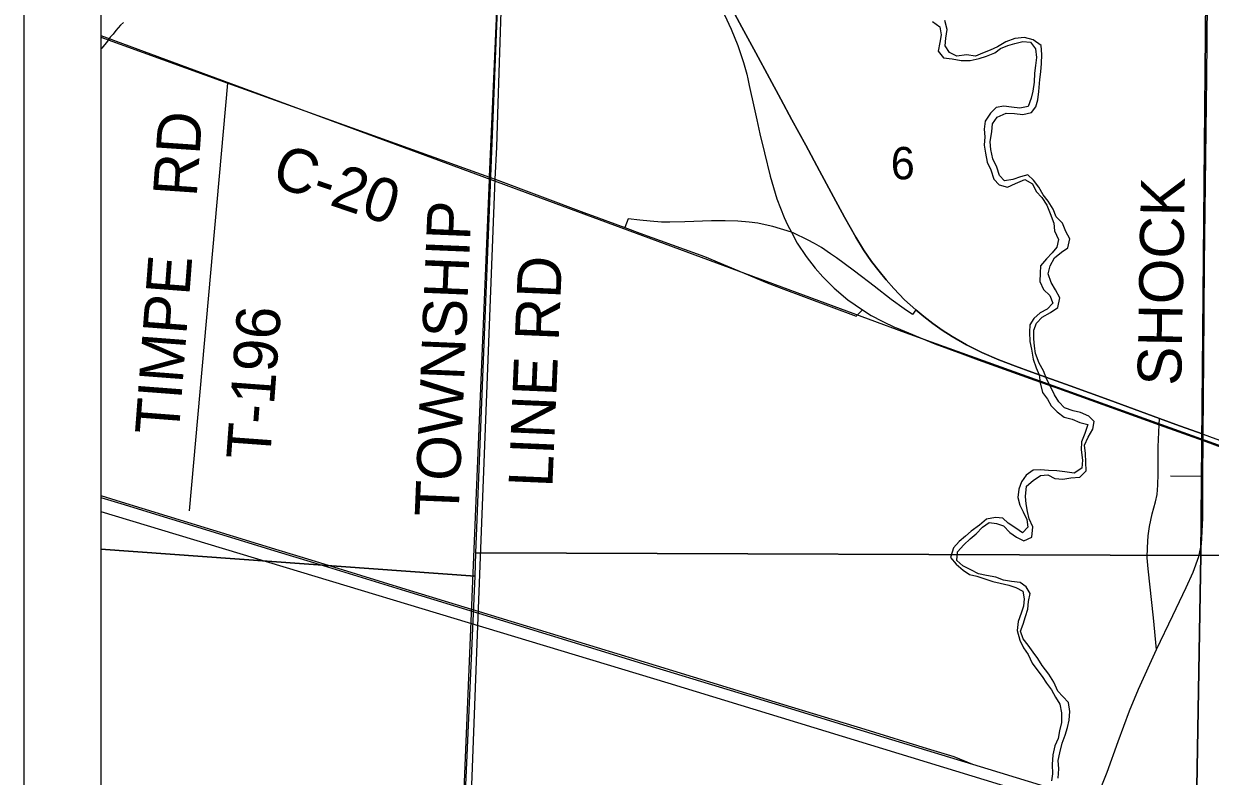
# Model space of a CAD drawing. Extents: x 0 to 34, y 0 to 22.
# Drawn here: x 2 to 3.538, y 19.175 to 20.151 of the extents above; entities that cross this region are included whole.
import ezdxf

# ---------------------------------------------------------------- set-up
doc = ezdxf.new("R2010")
doc.units = 0
for name, color, linetype in [('Default', 7, 'Continuous'), ('GM_X_County_Road', 7, 'Continuous'), ('GM_X_County_Road_Text', 7, 'Continuous'), ('GM_X_Interchange_Ramps', 7, 'Continuous'), ('GM_X_Minor_River', 7, 'Continuous'), ('GM_X_Rail_Line', 7, 'Continuous'), ('GM_X_Section', 7, 'Continuous'), ('GM_X_Section_Text', 7, 'Continuous'), ('GM_X_State_Route', 7, 'Continuous'), ('GM_X_Township', 7, 'Continuous'), ('GM_X_Township_Road', 7, 'Continuous'), ('GM_X_Township_Road_Text', 7, 'Continuous'), ('GM_X_US_Route', 7, 'Continuous'), ('SH_Cut_Line', 7, 'Continuous'), ('SH_Data', 7, 'Continuous')]:
    doc.layers.add(name, color=color, linetype=linetype)

msp = doc.modelspace()

# ---------------------------------------------------------------- linework, layer by layer
at = {"layer": 'Default'}
for points in [[(2.1, 20.3771), (2.1, 19.4698), (2.5849, 19.435), (2.5858, 19.465), (2.6217, 20.3656)], [(2.1, 19.4698), (2.1, 18.4416), (2.54, 18.4332), (2.5413, 18.4578), (2.5849, 19.435)]]:
    msp.add_lwpolyline(points, close=True, dxfattribs=at)
at = {"layer": 'GM_X_County_Road'}
for p, q in [((2.5885, 19.3706), (2.6108, 19.9494)), ((2.5733, 18.9746), (2.5885, 19.3706))]:
    msp.add_line(p, q, dxfattribs=at)
for points in [[(2.6108, 19.9494), (2.6132, 19.9909), (2.6147, 20.0477), (2.6187, 20.1666), (2.6231, 20.2904), (2.6255, 20.36), (2.6264, 20.3623)], [(2.1, 20.1336), (2.2644, 20.0739), (2.6038, 19.9519), (2.6108, 19.9494)], [(2.6108, 19.9494), (2.7293, 19.9049), (2.7321, 19.9039)], [(2.7321, 19.9039), (2.779, 19.8867), (2.7985, 19.8796)], [(2.7985, 19.8796), (2.8823, 19.8491), (2.9633, 19.8151)]]:
    msp.add_lwpolyline(points, dxfattribs=at)
at = {"layer": 'GM_X_Interchange_Ramps'}
for points in [[(3.0946, 19.8164), (3.0856, 19.8232), (3.075, 19.8317), (3.0533, 19.8474), (3.0456, 19.8528), (3.0337, 19.8608), (3.025, 19.866), (3.0158, 19.871), (2.9982, 19.8793), (2.9948, 19.8808), (2.971, 19.888), (2.961, 19.8904), (2.9513, 19.8922), (2.9401, 19.8938), (2.9255, 19.895), (2.9091, 19.8955), (2.8915, 19.8953), (2.8568, 19.894), (2.8375, 19.8937), (2.8265, 19.8939), (2.8119, 19.8948), (2.7983, 19.8962), (2.7834, 19.8982), (2.779, 19.8867)], [(2.9633, 19.8151), (2.9814, 19.8081), (3.079, 19.7719), (3.0869, 19.78)], [(3.1559, 19.7802), (3.1516, 19.7741), (3.1409, 19.7812), (3.1242, 19.7934), (3.102, 19.8108), (3.0946, 19.8164)]]:
    msp.add_lwpolyline(points, dxfattribs=at)
at = {"layer": 'GM_X_Minor_River'}
for points in [[(2.1295, 20.1527), (2.1253, 20.1493), (2.1192, 20.1421), (2.1157, 20.1376), (2.1122, 20.1335), (2.1084, 20.1282), (2.1011, 20.1192), (2.1, 20.1181)], [(3.1778, 20.1539), (3.1871, 20.1471), (3.1891, 20.1365), (3.1873, 20.1266), (3.1851, 20.1153), (3.1921, 20.1068), (3.2034, 20.1053), (3.2148, 20.1035), (3.2265, 20.1035), (3.2383, 20.1059), (3.2475, 20.1087), (3.2583, 20.1133), (3.266, 20.1188), (3.2752, 20.1227), (3.2844, 20.1255), (3.2947, 20.1279), (3.3045, 20.1272), (3.3111, 20.1183), (3.3123, 20.1073), (3.3113, 20.0967), (3.3099, 20.0868), (3.3096, 20.0754), (3.3077, 20.0637), (3.3056, 20.0543), (3.3015, 20.0438), (3.2908, 20.0414), (3.2799, 20.0428), (3.27, 20.0439), (3.2601, 20.0422), (3.2527, 20.0352), (3.246, 20.0248), (3.2446, 20.0142), (3.2454, 20.0043), (3.2448, 19.9937), (3.2464, 19.983), (3.2487, 19.9716), (3.2534, 19.9616), (3.2572, 19.9493), (3.2642, 19.9423), (3.2748, 19.9389), (3.2851, 19.944), (3.2974, 19.949), (3.3071, 19.9434), (3.3122, 19.9334), (3.3195, 19.9256), (3.3257, 19.9159), (3.33, 19.9048), (3.3349, 19.8925), (3.3358, 19.8826), (3.3408, 19.8714), (3.339, 19.8612), (3.3328, 19.8538), (3.3253, 19.846), (3.3175, 19.8372), (3.3173, 19.8277), (3.317, 19.817), (3.3216, 19.8063), (3.3297, 19.7985)], [(3.3468, 19.5607), (3.3571, 19.5623), (3.3685, 19.5631), (3.3767, 19.5713), (3.3766, 19.5827), (3.3758, 19.5937), (3.3749, 19.6047), (3.3794, 19.6149), (3.3854, 19.6253), (3.3871, 19.6355), (3.3801, 19.6422), (3.3696, 19.647), (3.3598, 19.6492), (3.3486, 19.6529), (3.3416, 19.6607), (3.3357, 19.67), (3.3311, 19.6796), (3.326, 19.6896), (3.3214, 19.7011), (3.316, 19.7111), (3.3114, 19.7234), (3.3098, 19.7329), (3.3089, 19.7425), (3.3092, 19.7535), (3.3125, 19.7629), (3.3199, 19.7706), (3.3307, 19.7768), (3.3403, 19.783), (3.3426, 19.7958), (3.3372, 19.8059), (3.3313, 19.8155), (3.3275, 19.8266), (3.33, 19.8372), (3.336, 19.8473), (3.3449, 19.855), (3.353, 19.8605), (3.3556, 19.8722), (3.3506, 19.8818), (3.3463, 19.8926), (3.3378, 19.9008), (3.3339, 19.9107), (3.3278, 19.9208), (3.3212, 19.9293), (3.3154, 19.9393), (3.3088, 19.9483), (3.3014, 19.9549), (3.2918, 19.9525), (3.2819, 19.949), (3.2712, 19.9474), (3.2646, 19.9544), (3.2611, 19.9651), (3.2561, 19.9759), (3.2533, 19.9878), (3.2525, 19.998), (3.2544, 20.0113), (3.2554, 20.0211), (3.2613, 20.0297), (3.2732, 20.035), (3.2838, 20.0344), (3.2948, 20.0333), (3.3058, 20.0357), (3.3117, 20.0431), (3.3143, 20.0525), (3.3157, 20.0631), (3.3169, 20.0787), (3.3183, 20.0885), (3.3189, 20.0995), (3.3192, 20.1109), (3.3184, 20.1227), (3.308, 20.1302), (3.2971, 20.1331), (3.2842, 20.1316), (3.2727, 20.1273), (3.2619, 20.1208), (3.2523, 20.1169), (3.2423, 20.1126), (3.2335, 20.109), (3.2218, 20.1105), (3.2092, 20.1089), (3.1999, 20.1138), (3.194, 20.1223), (3.1951, 20.1321), (3.1969, 20.1435), (3.1938, 20.1553)], [(3.3297, 19.7985), (3.3337, 19.7885), (3.3262, 19.7811), (3.3174, 19.776), (3.3092, 19.7687), (3.3037, 19.7608), (3.3034, 19.7513), (3.3039, 19.7392), (3.3059, 19.7289), (3.3082, 19.7163), (3.312, 19.7048), (3.316, 19.6959), (3.3172, 19.6853), (3.3203, 19.673), (3.3269, 19.6641), (3.3316, 19.6557), (3.3393, 19.6478), (3.3482, 19.6411), (3.3588, 19.6382), (3.3685, 19.6338), (3.3791, 19.6312), (3.375, 19.6199), (3.3709, 19.609), (3.3702, 19.5984), (3.3721, 19.5851), (3.3711, 19.5748), (3.3614, 19.5683), (3.349, 19.5701), (3.3388, 19.5712), (3.3282, 19.5718), (3.3176, 19.5725), (3.3081, 19.572), (3.2992, 19.5658), (3.2929, 19.5572), (3.2896, 19.5475), (3.2882, 19.5369), (3.2909, 19.5269), (3.2952, 19.5181), (3.2999, 19.5084), (3.3011, 19.4985), (3.2945, 19.4908), (3.2859, 19.4971), (3.2759, 19.5034), (3.2688, 19.5101), (3.2594, 19.5107), (3.2476, 19.5087), (3.2386, 19.501), (3.2278, 19.493), (3.2204, 19.4867), (3.2123, 19.4797), (3.2049, 19.4716), (3.2011, 19.4588), (3.2085, 19.4502), (3.2173, 19.4424), (3.2255, 19.4368), (3.235, 19.4347), (3.2455, 19.4313), (3.256, 19.428), (3.2654, 19.4259), (3.2767, 19.4233), (3.2857, 19.42), (3.2947, 19.4152), (3.2967, 19.4056), (3.2957, 19.3958), (3.2924, 19.3868), (3.2887, 19.3762), (3.2873, 19.3645), (3.2907, 19.3519), (3.2958, 19.3419), (3.3016, 19.3334), (3.307, 19.3222), (3.3128, 19.3137), (3.3198, 19.3048), (3.3256, 19.2959), (3.3318, 19.2874), (3.3373, 19.2781), (3.3427, 19.2688), (3.3447, 19.2578), (3.3447, 19.2452), (3.3422, 19.2343), (3.3404, 19.2245), (3.3363, 19.2147), (3.3337, 19.203), (3.333, 19.1905), (3.3331, 19.1787), (3.332, 19.1693)], [(3.2995, 19.5514), (3.3081, 19.5587), (3.3177, 19.5653), (3.3273, 19.5662), (3.3362, 19.5614), (3.3468, 19.5607)], [(3.3405, 19.1728), (3.3416, 19.185), (3.3407, 19.196), (3.3429, 19.2058), (3.3459, 19.2182), (3.3496, 19.2288), (3.3525, 19.2386), (3.3547, 19.248), (3.3557, 19.2594), (3.3541, 19.2712), (3.3468, 19.2786), (3.3401, 19.2856), (3.3351, 19.2975), (3.3286, 19.3079), (3.3198, 19.3188), (3.3144, 19.3281), (3.3081, 19.3362), (3.3019, 19.3455), (3.2953, 19.3537), (3.2918, 19.3633), (3.2951, 19.3727), (3.2984, 19.3824), (3.3013, 19.3922), (3.3023, 19.4021), (3.3041, 19.4123), (3.2991, 19.4211), (3.2912, 19.4267), (3.2803, 19.4281), (3.2697, 19.4295), (3.2596, 19.4336), (3.2475, 19.4355), (3.2373, 19.438), (3.2272, 19.4432), (3.2171, 19.4481), (3.2093, 19.4551), (3.21, 19.4665), (3.2182, 19.4754), (3.2264, 19.4831), (3.2342, 19.4897), (3.2427, 19.4982), (3.2513, 19.5045), (3.2607, 19.5031), (3.2697, 19.5002), (3.2778, 19.4912), (3.2864, 19.4853), (3.2961, 19.4805), (3.3065, 19.4855), (3.3076, 19.4987), (3.303, 19.5091), (3.3009, 19.5187), (3.2989, 19.5286), (3.2984, 19.5381), (3.2995, 19.5514)]]:
    msp.add_lwpolyline(points, dxfattribs=at)
at = {"layer": 'GM_X_Rail_Line'}
for points in [[(2.1, 20.1355), (2.5574, 19.9667), (3.1422, 19.7506), (3.6996, 19.5506), (4.3507, 19.3207), (4.9212, 19.1118), (5.8157, 18.7674), (6.212, 18.6139), (6.6644, 18.4531), (7.3247, 18.2205), (7.6757, 18.0934)], [(2.1, 19.5392), (2.1263, 19.5312), (2.3304, 19.4687), (2.3719, 19.4559), (2.4953, 19.4178), (2.5902, 19.389), (2.8196, 19.3188), (2.9846, 19.2683), (3.09, 19.2363), (3.1707, 19.2116), (3.2055, 19.2009), (3.2297, 19.1911)], [(2.1, 19.5368), (2.1257, 19.529), (2.3297, 19.4665), (2.3712, 19.4537), (2.4946, 19.4156), (2.5895, 19.3868), (2.8189, 19.3166), (2.9839, 19.2661), (3.0893, 19.234), (3.17, 19.2094), (3.2494, 19.1851), (3.3541, 19.1532), (3.437, 19.1279), (3.5117, 19.1049), (3.7206, 19.0413), (3.9442, 18.9731), (4.115, 18.921), (4.2732, 18.8725), (4.3809, 18.8396), (4.4591, 18.8158), (4.5185, 18.7976), (5.0181, 18.6458)], [(2.1, 19.5186), (2.8346, 19.2964), (3.6748, 19.0394), (4.5141, 18.7823), (5.7652, 18.3991), (6.2109, 18.2673), (6.7654, 18.1025), (7.4524, 17.8921)]]:
    msp.add_lwpolyline(points, dxfattribs=at)
at = {"layer": 'GM_X_Section'}
for points in [[(4.5401, 20.4008), (4.5252, 19.4639), (3.5253, 19.4614), (3.5337, 20.3786), (3.5682, 20.3787)], [(3.5337, 20.3786), (3.5253, 19.4614), (2.5858, 19.465), (2.6217, 20.3656)], [(3.5253, 19.4614), (3.5082, 18.4594), (2.5413, 18.4578), (2.5849, 19.435), (2.5858, 19.465)], [(4.5252, 19.4639), (4.517, 18.4555), (3.5082, 18.4594), (3.5253, 19.4614)]]:
    msp.add_lwpolyline(points, close=True, dxfattribs=at)
at = {"layer": 'GM_X_State_Route'}
for points in [[(3.1559, 19.7802), (3.1414, 19.7932), (3.1274, 19.8079), (3.1176, 19.8189), (3.1084, 19.8301), (3.0985, 19.8429), (3.0883, 19.8578), (3.0783, 19.8741), (3.0636, 19.9004), (3.0493, 19.9267), (3.0313, 19.9601), (3.0134, 19.9934), (2.9956, 20.0263), (2.981, 20.0533), (2.9664, 20.0805), (2.9487, 20.1133), (2.9307, 20.1466), (2.9125, 20.1804)], [(3.4719, 19.6394), (3.4061, 19.6633), (3.3559, 19.6814), (3.3066, 19.6993), (3.2853, 19.7071), (3.2638, 19.7153), (3.2416, 19.7249), (3.2219, 19.7346), (3.2034, 19.7453), (3.1904, 19.7537), (3.1781, 19.7624), (3.1663, 19.7713), (3.1559, 19.7802)], [(3.5284, 19.619), (3.4979, 19.6299), (3.4719, 19.6394)], [(3.397, 19.1634), (3.4039, 19.1808), (3.4183, 19.2206), (3.4328, 19.2603), (3.4448, 19.2882), (3.468, 19.3398), (3.4893, 19.3837), (3.5064, 19.4201), (3.5154, 19.4402), (3.5227, 19.4604), (3.5261, 19.4765), (3.5273, 19.4927), (3.5279, 19.5098), (3.528, 19.5642), (3.5283, 19.6107)], [(3.5283, 19.6107), (3.5283, 19.6137), (3.5284, 19.619)]]:
    msp.add_lwpolyline(points, dxfattribs=at)
at = {"layer": 'GM_X_Township'}
msp.add_lwpolyline([(2.5093, 17.4289), (2.5256, 18.0846), (2.5616, 18.9348), (2.5619, 18.941), (2.5631, 18.9701), (2.6034, 19.9491), (2.6035, 19.9525), (2.6217, 20.3636), (2.6265, 20.3636), (2.7999, 20.363), (2.8069, 20.3629), (2.814, 20.3628), (2.8217, 20.3627), (3.5356, 20.3768), (3.5731, 20.3768), (3.6279, 20.3774), (4.0307, 20.3846), (4.54, 20.3955), (4.5784, 20.3968), (5.284, 20.4086)], dxfattribs=at)
at = {"layer": 'GM_X_Township_Road'}
for p, q in [((2.2148, 19.5194), (2.2644, 20.0739)), ((3.528, 19.5642), (3.4861, 19.5644))]:
    msp.add_line(p, q, dxfattribs=at)
for points in [[(3.5284, 19.619), (3.5292, 19.7152), (3.5303, 19.8391), (3.5333, 20.0814), (3.5359, 20.3762)], [(2.4116, 15.0173), (2.4334, 15.5145), (2.4339, 15.5244), (2.4986, 16.925), (2.5003, 16.9626), (2.5093, 17.4289), (2.5256, 18.0846), (2.5616, 18.9348), (2.5619, 18.941), (2.5631, 18.9701), (2.6034, 19.9491), (2.6035, 19.9525), (2.6217, 20.3636), (2.1208, 20.3735), (2.1108, 20.3737), (2.1, 20.3739), (2.1, 14.5206)], [(3.468, 19.3398), (3.4642, 19.3809), (3.4572, 19.4441), (3.456, 19.4587), (3.4563, 19.4719), (3.4574, 19.487), (3.459, 19.4993), (3.4622, 19.5155), (3.4668, 19.531), (3.4687, 19.5406), (3.4697, 19.5529), (3.4702, 19.5675), (3.4703, 19.6023), (3.4714, 19.6308), (3.4719, 19.6394)]]:
    msp.add_lwpolyline(points, dxfattribs=at)
at = {"layer": 'GM_X_US_Route'}
for points in [[(2.9019, 20.1745), (2.9081, 20.1626), (2.9168, 20.144), (2.9255, 20.1228), (2.9329, 20.1006), (2.9369, 20.0855), (2.9383, 20.0796)], [(2.9125, 20.1804), (2.9307, 20.1466), (2.9487, 20.1133), (2.9664, 20.0805), (2.981, 20.0533), (2.9956, 20.0263), (3.0134, 19.9934), (3.0313, 19.9601), (3.0493, 19.9267), (3.0636, 19.9004), (3.0783, 19.8741), (3.0883, 19.8578), (3.0985, 19.8429), (3.1084, 19.8301), (3.1176, 19.8189), (3.1274, 19.8079), (3.1414, 19.7932), (3.1559, 19.7802)], [(2.9383, 20.0796), (2.9403, 20.0708), (2.9467, 20.0418), (2.9502, 20.0263), (2.9514, 20.0203)], [(2.9514, 20.0203), (2.9539, 20.0082), (2.9599, 19.9834), (2.9674, 19.9534), (2.976, 19.924), (2.9856, 19.8996), (2.9897, 19.8902), (2.9948, 19.8808), (3.0023, 19.8667), (3.0138, 19.8494), (3.0256, 19.8342), (3.0356, 19.823), (3.0503, 19.8083), (3.0681, 19.7931), (3.0869, 19.78)], [(3.0869, 19.78), (3.0984, 19.7728), (3.1125, 19.7652), (3.1293, 19.7573), (3.1311, 19.7566)], [(3.1559, 19.7802), (3.1663, 19.7713), (3.1781, 19.7624), (3.1904, 19.7537), (3.2034, 19.7453), (3.2219, 19.7346), (3.2416, 19.7249), (3.2638, 19.7153), (3.2853, 19.7071), (3.3066, 19.6993), (3.3559, 19.6814), (3.4061, 19.6633), (3.4719, 19.6394)], [(3.1311, 19.7566), (3.1806, 19.7362), (3.2162, 19.7231), (3.237, 19.7154), (3.3105, 19.6891)], [(3.3105, 19.6891), (3.3363, 19.6798), (3.4714, 19.6308), (3.5283, 19.6107), (3.5739, 19.594)], [(3.4719, 19.6394), (3.4979, 19.6299), (3.5284, 19.619)], [(3.5284, 19.619), (3.558, 19.6082), (3.6005, 19.5929), (3.6861, 19.5619), (3.7288, 19.5464), (3.7751, 19.53), (3.8144, 19.5161), (3.8701, 19.4967), (3.9561, 19.4662), (3.9858, 19.4556), (4.0196, 19.4438)]]:
    msp.add_lwpolyline(points, dxfattribs=at)
at = {"layer": 'SH_Cut_Line'}
msp.add_lwpolyline([(8.9, 20.9), (2.1, 20.9), (2.1, 14.5206)], dxfattribs=at)
at = {"layer": 'SH_Data'}
for p, q in [((2, 21), (2, 14)), ((2.1, 20.9), (2.1, 14.1))]:
    msp.add_line(p, q, dxfattribs=at)

# ---------------------------------------------------------------- texts
at = {"layer": 'GM_X_County_Road_Text'}
for s, rotation, p in [('C-20', 341.1304, (2.3188, 19.9425)), ('TOWNSHIP', 87.6083, (2.5634, 19.511)), ('LINE RD', 87.541, (2.685, 19.5492))]:
    msp.add_text(s, height=0.05682, rotation=rotation, dxfattribs=at).set_placement(p)
at = {"layer": 'GM_X_Section_Text'}
msp.add_text('6', height=0.0419, rotation=0, dxfattribs=at).set_placement((3.1236, 19.9493))
at = {"layer": 'GM_X_Township_Road_Text'}
for s, rotation, p in [('RD', 86.0551, (2.2241, 19.9257)), ('SHOCK', 88.984, (3.5, 19.6813)), ('TIMPE', 85.6371, (2.2008, 19.6167)), ('T-196', 85.7948, (2.3191, 19.5845))]:
    msp.add_text(s, height=0.05682, rotation=rotation, dxfattribs=at).set_placement(p)

doc.saveas('drawing.dxf')
